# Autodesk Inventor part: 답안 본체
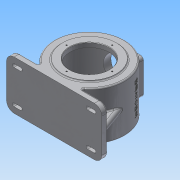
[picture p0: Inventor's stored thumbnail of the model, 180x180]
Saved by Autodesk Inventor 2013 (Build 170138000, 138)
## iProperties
Created: 2015-06
Part Number: 답안 본체
Material: 알루미늄 6061
Document SubType Name: Modeling
Designer: Administrator
Density: 2.71 g/cm^3
Mass: 3270.96 g
Surface Area: 2314.15 cm^2
Volume: 1207 cm^3
Author: Administrator
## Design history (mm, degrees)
sketch "스케치1"
  geometry: L1 (115, 14)-(115, 0); L2 (115, 0)-(-115, 0); L3 (-115, 0)-(-115, 14); L4 (-115, 14)-(-46.733, 14); L5 (46.733, 14)-(115, 14); A1 r 85 centre (0, 85) between (46.733, 14) and (-46.733, 14); 2 further points
  constraints: 10 end point, 3 parallel, 2 coincident, 2 horizontal, 2 perpendicular, 2 point on circle, 1 centre point, 1 collinear, 1 midpoint, 1 vertical alignment
  dimensions: "d1" = 85 distance of point (0, 0) A1.centre; "d2" = 230 distance between parallel lines of L1 L3; "d4" = 85 radius of A1; "d5" = 14 distance between parallel lines of L2 L5
extrude "돌출1" new body sketch "스케치1" distance "d6" = 118; taper "d7" = 0 deg
fillet "모깎기1" dims "d8" = 3
fillet "모깎기2" dims "d9" = 18
sketch "스케치2"
  geometry: L1 (-97, 0)-(97, 0) reference; C1 r 65 at (0, 85); A1 r 85 centre (0, 85) between (53.953, 19.318) and (-53.953, 19.318) reference; 2 further points
  constraints: 1 centre point, 1 coincident, 1 midpoint, 1 vertical alignment
  dimensions: "d10" = 130 diameter of C1
extrude "돌출2" join sketch "스케치2" distance "d11" = 3; taper "d12" = 0 deg
hole "구멍1" diameter "d15" = 95; stored, may be unused: countersink angle "d19" = 90 deg, drill point angle "d21" = 0 deg; dims "d13" = 10, "d14" = 10, "d16" = 6, "d17" = 4, "d18" = 2, "d20" = 11
sketch "스케치3"
  geometry: C1 r 77 at (0, 0); A1 r 85 centre (0, 0) between (53.953, -65.682) and (-53.953, -65.682) reference; 1 further point
  constraints: 1 centre point, 1 coincident
  dimensions: "d22" = 154 diameter of C1
extrude "돌출3" cut sketch "스케치3" distance "d23" = 102; taper "d24" = 0 deg
sketch "스케치4"
  geometry: C1 r 47.5 at (0, 0) reference; 2 further points
  constraints: 1 vertical alignment
  dimensions: "d25" = 55 distance of point (0, 55) C1.centre
hole "구멍2" sketch "스케치4" at (0, 55) diameter "d26" = 3.242; stored, may be unused: countersink angle "d30" = 90 deg, drill point angle "d32" = 0 deg; dims "d27" = 6, "d28" = 4, "d29" = 2, "d31" = 12
sketch "스케치5"
  geometry: C1 r 31 at (0, 0); A1 r 85 centre (0, 0) between (53.953, -65.682) and (-53.953, -65.682) reference; 1 further point
  constraints: 1 centre point, 1 coincident
  dimensions: "d36" = 62 diameter of C1
extrude "돌출4" join sketch "스케치5" distance "d37" = 3.5; taper "d38" = 0 deg
feature "면 기울기1" dims angle "d41" = 25 deg
sketch "스케치7"
  geometry: C1 r 65 at (0, 85); A1 r 85 centre (0, 85) between (53.953, 19.318) and (-53.953, 19.318) reference; 1 further point
  constraints: 1 centre point, 1 coincident
  dimensions: "d42" = 130 diameter of C1
extrude "돌출6" join sketch "스케치7" distance "d43" = 13; taper "d44" = 0 deg
hole "구멍3" diameter "d47" = 30; stored, may be unused: countersink angle "d51" = 90 deg, drill point angle "d53" = 0 deg; dims "d45" = 10, "d46" = 10, "d48" = 6, "d49" = 47, "d50" = 14, "d52" = 17
fillet "모깎기3" dims "d54" = 0.3
fillet "모깎기4" dims "d55" = 3
node "작업 평면2"
  node "작업 평면1"
sketch "스케치8"
  geometry: L1 (42.5, 16.5)-(-42.5, 16.5); L2 (-42.5, 16.5)-(-42.5, 101.5); L3 (-42.5, 101.5)-(42.5, 101.5); L4 (42.5, 101.5)-(42.5, 16.5); L5 (115, 18)-(115, 100) reference; 4 further points
  constraints: 8 end point, 3 midpoint, 2 parallel, 1 horizontal, 1 horizontal alignment, 1 perpendicular, 1 vertical alignment
  dimensions: "d57" = 85 distance of L1.start L1.end; "d59" = 85 distance of L1.end L2.end
extrude "돌출7" join sketch "스케치8" stored distance "d60" = 13; taper "d61" = 0 deg
sketch "스케치9"
  geometry: L1 (-42.5, -101.5)-(-42.5, -16.5) reference; L2 (-35.5, -23.5)-(35.5, -23.5); L3 (35.5, -23.5)-(35.5, -94.5); L4 (35.5, -94.5)-(-35.5, -94.5); L5 (-35.5, -94.5)-(-35.5, -23.5); 8 further points
  constraints: 8 end point, 3 coincident, 3 midpoint, 2 parallel, 1 horizontal, 1 horizontal alignment, 1 perpendicular, 1 point on line, 1 vertical alignment
  dimensions: "d62" = 71 distance of L2.start L2.end; "d64" = 71 distance of L2.end L3.end
hole "구멍4" sketch "스케치9" at (-35.5, -23.5), (-35.5, -94.5), (33.456, -94.5), (35.5, -23.5) diameter "d65" = 3.242; stored, may be unused: countersink angle "d69" = 90 deg, drill point angle "d71" = 118 deg; dims "d66" = 10, "d67" = 47, "d68" = 14, "d70" = 13
sketch "스케치10"
  geometry: L1 (-42.5, -101.5)-(-42.5, -16.5) reference; 3 further points
  constraints: 1 horizontal alignment, 1 midpoint, 1 vertical alignment
hole "구멍5" sketch "스케치10" at (0, -59) diameter "d72" = 70; stored, may be unused: countersink angle "d76" = 90 deg, drill point angle "d78" = 0 deg; dims "d73" = 10, "d74" = 47, "d75" = 14, "d77" = 13
fillet "모깎기5" dims "d79" = 7
sketch "스케치11"
  geometry: L1 (25.143, 109)-(41.143, 109); L2 (41.143, 91)-(25.143, 91); L3 (25.143, 27)-(41.143, 27); L4 (41.143, 9)-(25.143, 9); A1 r 18 centre (41.143, 100) between (59.143, 100) and (41.143, 118) reference; A2 r 18 centre (41.143, 18) between (41.143, 0) and (59.143, 18) reference; A3 r 9 centre (41.143, 100) between (41.143, 91) and (41.143, 109); A4 r 9 centre (25.143, 100) between (25.143, 109) and (25.143, 91); A5 r 9 centre (41.143, 18) between (41.143, 9) and (41.143, 27); A6 r 9 centre (25.143, 18) between (25.143, 27) and (25.143, 9); 1 further point
  constraints: 8 end point, 8 point on circle, 8 tangent, 4 centre point, 3 parallel, 1 coincident, 1 concentric, 1 horizontal, 1 horizontal alignment
  dimensions: "d81" = 16 distance of A1.centre A4.centre; "d82" = 16 distance of A2.centre A6.centre; "d83" = 18 distance between parallel lines of L2 L1; "d84" = 18 distance between parallel lines of L4 L3
extrude "돌출8" join sketch "스케치11" distance "d85" = 3; taper "d86" = 0 deg
sketch "스케치12"
  geometry: L1 (41.143, 91)-(25.143, 91) reference; L2 (25.143, 109)-(41.143, 109) reference; L3 (41.143, 9)-(25.143, 9) reference; L4 (25.143, 27)-(41.143, 27) reference; L5 (41.143, 118)-(0, 118) reference; L6 (0, 0)-(0, 118) reference; L7 (41.143, 0)-(0, 0) reference; L8 (59.143, 100)-(59.143, 18) reference; L9 (41.143, 96)-(25.143, 96); L10 (25.143, 104)-(41.143, 104); L11 (41.143, 14)-(25.143, 14); L12 (25.143, 22)-(41.143, 22); A1 r 9 centre (41.143, 100) between (41.143, 91) and (41.143, 109) reference; A2 r 9 centre (25.143, 100) between (25.143, 109) and (25.143, 91) reference; A3 r 9 centre (41.143, 18) between (41.143, 9) and (41.143, 27) reference; A4 r 9 centre (25.143, 18) between (25.143, 27) and (25.143, 9) reference; A5 r 18 centre (41.143, 100) between (59.143, 100) and (41.143, 118) reference; A6 r 18 centre (41.143, 18) between (41.143, 0) and (59.143, 18) reference; A7 r 4 centre (41.143, 100) between (41.143, 96) and (41.143, 104); A8 r 4 centre (25.143, 100) between (25.143, 104) and (25.143, 96); A9 r 4 centre (41.143, 18) between (41.143, 14) and (41.143, 22); A10 r 4 centre (25.143, 18) between (25.143, 22) and (25.143, 14); 1 further point
  constraints: 8 end point, 8 point on circle, 4 centre point, 6 other
  dimensions: "d87" = 8 distance between parallel lines of L11 L12; "d89" = 8 distance between parallel lines of L9 L10
extrude "돌출9" cut sketch "스케치12" stored distance "d90" = 0; taper "d91" = 0 deg
node "작업 평면3"
sketch "스케치13"
  geometry: L1 (97, 14)-(115, 14) reference; L2 (115, 14)-(115, 0) reference; L3 (109, 14)-(84.87, 80.297); A1 r 85 centre (0, 85) between (53.953, 19.318) and (-53.953, 19.318) reference; 1 further point
  constraints: 2 end point, 1 point on circle, 1 point on line
  dimensions: "d92" = 110 deg angle of L3 L1; "d93" = 6 distance from line of L2 L3.start
feature "리브1" sketch "스케치13" dims "d94" = 1, "d95" = 15, "d96" = 0, "d97" = 0, "d98" = 1, "d99" = 1
fillet "모깎기6" dims "d100" = 7.5
chamfer "모따기1" distance "d101" = 1; stored, may be unused: second distance "d102" = 2, angle "d103" = 45 deg
fillet "모깎기7" dims "d104" = 3
node "작업 평면4"
sketch "스케치14"
  geometry: L1 (77.036, 120.923)-(0, 85); L2 (0, 85)-(85, 85); A1 r 85 centre (0, 85) between (53.953, 19.318) and (-53.953, 19.318) reference; 1 further point
  constraints: 4 end point, 2 point on circle, 1 horizontal
  dimensions: "d105" = 25 deg angle of L1 L2
node "작업 평면6"
  node "작업 평면5"
sketch "스케치15"
  geometry: L1 (-79.424, 59)-(82, 59) reference; L2 (65, 62)-(-65, 62) reference; 4 further points
  constraints: 1 midpoint, 1 vertical alignment, 1 other
  dimensions: "d107" = 59 distance from line of L1 point (0, 0)
feature "엠보싱1" sketch "스케치15" dims "d1" = 85, "d2" = 230, "d4" = 85, "d5" = 14, "d108" = 0.5, "d109" = 0
node "솔리드1"
pattern_circular "원형 패턴1" dims angle "d34" = 360 deg
mirror "대칭1"
mirror "대칭2"
node "투영된 루프2"
other parameters: "d3" = 14, "d56" = 3, "d106" = 5
